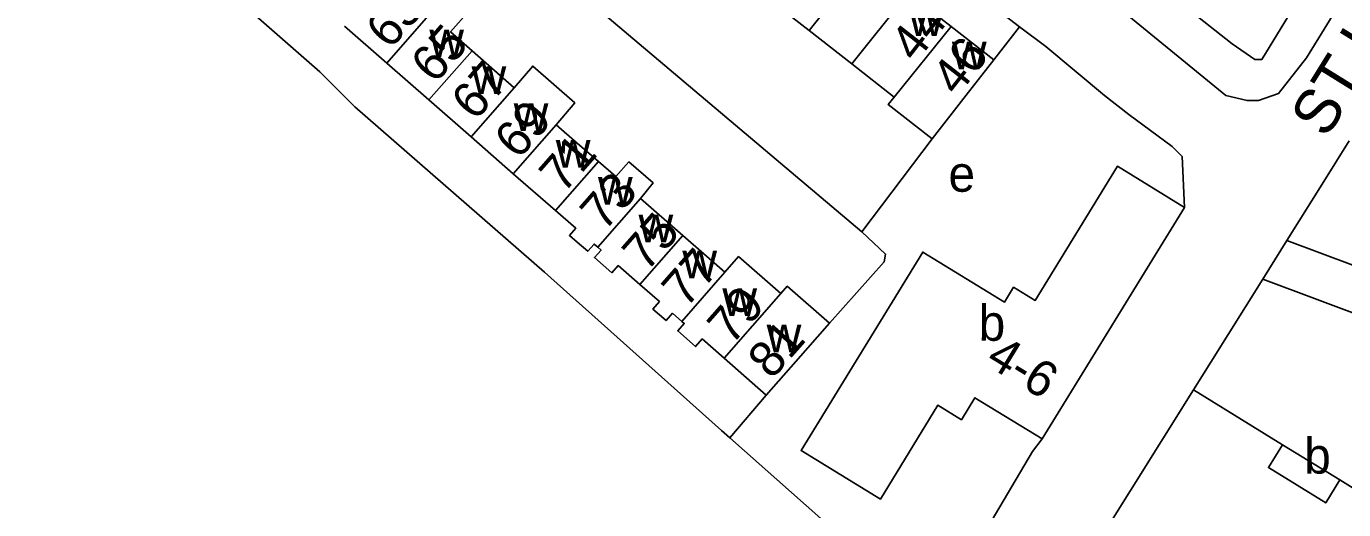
# Model space of a CAD drawing. Extents: x 162804 to 165059, y 381530 to 382901.
# Drawn here: x 162938.5 to 163085.6, y 381854.4 to 381908.3 of the extents above; entities that cross this region are included whole.
import ezdxf

# ---------------------------------------------------------------- set-up
doc = ezdxf.new("R2010")
doc.units = 0
for name, color, linetype in [('BLT_Basislijn', 7, 'Continuous'), ('BLT_Bebouwing', 7, 'Continuous'), ('BLT_Centroide', 7, 'Continuous'), ('BLT_Huisnummer', 7, 'Continuous'), ('BLT_Huisnummer_ tussenligend', 7, 'Continuous'), ('BLT_Huisnummer_reeks', 7, 'Continuous'), ('BLT_Onderverdeling_panden', 7, 'Continuous'), ('BLT_Straatnaam', 7, 'Continuous')]:
    doc.layers.add(name, color=color, linetype=linetype)

msp = doc.modelspace()

# ---------------------------------------------------------------- linework, layer by layer
at = {"layer": 'BLT_Basislijn'}
for p, q in [((162982.74, 381926.86), (163031.79, 381885.39)), ((163046.52, 381904.6), (163049.39, 381908.29)), ((163058.86, 381900.61), (163061.6, 381898.48)), ((163031.79, 381885.39), (163039.63, 381895.79)), ((163083.34, 381891.02), (163086.18, 381895.57)), ((163079.23, 381884.44), (163083.34, 381891.02)), ((163076.53, 381880.11), (163079.23, 381884.44)), ((163068.81, 381867.75), (163076.53, 381880.11)), ((163017.03, 381862.36), (163021.12, 381867.16)), ((163051.03, 381839.3), (163068.81, 381867.75)), ((163078.76, 381861.61), (163068.81, 381867.75)), ((163085.15, 381857.68), (163092.38, 381853.12))]:
    msp.add_line(p, q, dxfattribs=at)
for points in [[(163142.62, 381959.14), (163116.47, 381889.89), (163110.52, 381874.65), (163109.75, 381873.99), (163108.12, 381873.63), (163079.23, 381884.44)], [(163104.58, 381951.95), (163107.72, 381949.86), (163108.33, 381948.97), (163107.96, 381947.96), (163081.42, 381904.82), (163078.3, 381900.84), (163076.07, 381900.06), (163074.79, 381900.06), (163072.4, 381900.61), (163058.73, 381911.86), (163052.24, 381916.83)], [(163104.58, 381951.95), (163102.76, 381948.29), (163098.1, 381940.15), (163076.45, 381904.65), (163075.65, 381904.65), (163073.11, 381906.41), (163055.05, 381920.69)], [(163049.39, 381908.29), (163048.27, 381909.14), (163024.93, 381927.03), (163020.58, 381930.61), (162999.06, 381947.28)], [(162933.29, 381940.41), (162931.69, 381938.6), (162943.06, 381927.99), (162971.29, 381903.26), (162975.18, 381899.34), (162996.37, 381880.88), (163016.11, 381863.18), (163017.03, 381862.36)], [(163049.39, 381908.29), (163052.32, 381906.08), (163058.86, 381900.61)], [(163067.81, 381888.12), (163067.53, 381893.82), (163066.42, 381894.91), (163061.6, 381898.48)], [(163031.79, 381885.39), (163034.44, 381882.91), (163034.28, 381882.02), (163028.16, 381875.19)], [(163104.6, 381849.45), (163107.64, 381865.58), (163108.17, 381867.76), (163107.76, 381868.42), (163076.53, 381880.11)], [(163051.91, 381862.27), (163050.85, 381860.84), (163040.25, 381842.95), (163039.32, 381842.6), (163017.03, 381862.36)]]:
    msp.add_lwpolyline(points, dxfattribs=at)
at = {"layer": 'BLT_Bebouwing'}
for p, q in [((163021.15, 381911.59), (163025.9, 381907.87)), ((163036.97, 381912.07), (163041.74, 381908.34)), ((162974.03, 381908.36), (162978.74, 381904.24)), ((163041.74, 381908.34), (163046.52, 381904.6)), ((162992.97, 381901.48), (162988.27, 381905.61)), ((162978.74, 381904.24), (162983.45, 381900.12)), ((163030.65, 381904.16), (163035.4, 381900.45)), ((162983.45, 381900.12), (162988.16, 381896)), ((162988.16, 381896), (162992.87, 381891.88)), ((162992.87, 381891.88), (162997.58, 381887.77)), ((163007.09, 381889.11), (163011.79, 381884.99)), ((163011.79, 381884.99), (163016.5, 381880.87)), ((163016.41, 381871.29), (163021.12, 381867.16)), ((163085.15, 381857.68), (163078.76, 381861.61))]:
    msp.add_line(p, q, dxfattribs=at)
for points in [[(162988.27, 381905.61), (162985.88, 381907.74), (162988.19, 381910.38), (162985.88, 381912.39)], [(163025.9, 381907.87), (163030.65, 381904.16)], [(162997.67, 381897.36), (162999.74, 381899.8), (162995.05, 381903.91), (162992.97, 381901.48)], [(163039.63, 381895.79), (163043.44, 381900.66), (163046.52, 381904.6)], [(163035.4, 381900.45), (163034.74, 381899.6), (163039.63, 381895.79)], [(163002.38, 381893.23), (163000, 381895.31), (162997.67, 381897.36)], [(163002.38, 381893.23), (163004.33, 381891.56), (163005.77, 381893.21), (163008.47, 381890.85), (163007.09, 381889.11)], [(163051.91, 381862.27), (163044.41, 381866.86), (163042.9, 381864.39), (163040.26, 381866.01), (163033.86, 381855.54), (163025.01, 381860.95), (163038.58, 381883.13), (163047.71, 381877.54), (163048.73, 381879.2), (163051.14, 381877.72), (163060.31, 381892.71), (163067.81, 381888.12)], [(162997.58, 381887.77), (162999.84, 381885.79), (162999.14, 381884.99), (163000, 381884.25), (163001.18, 381883.22), (163001.89, 381884.03), (163002.3, 381883.66)], [(163067.81, 381888.12), (163051.91, 381862.27)], [(163002.3, 381883.66), (163002.67, 381883.35), (163001.93, 381882.51), (163003.87, 381880.81), (163004.59, 381881.62), (163006.99, 381879.52)], [(163016.5, 381880.87), (163018.03, 381882.62), (163022.74, 381878.5)], [(163006.99, 381879.52), (163009.19, 381877.6), (163008.46, 381876.76), (163009.93, 381875.48), (163010.65, 381876.3), (163011.69, 381875.39)], [(163022.74, 381878.5), (163023.45, 381879.31), (163028.16, 381875.19)], [(163011.69, 381875.39), (163011.96, 381875.16), (163011.23, 381874.32), (163013.23, 381872.57), (163013.97, 381873.42), (163016.41, 381871.29)], [(163021.12, 381867.16), (163024.42, 381870.92), (163028.16, 381875.19)], [(163078.76, 381861.61), (163077.18, 381859.05), (163083.57, 381855.11), (163085.15, 381857.68)]]:
    msp.add_lwpolyline(points, dxfattribs=at)
at = {"layer": 'BLT_Onderverdeling_panden'}
for p, q in [((163025.9, 381907.87), (163032.19, 381915.8)), ((162978.74, 381904.24), (162985.88, 381912.39)), ((163030.65, 381904.16), (163036.97, 381912.07)), ((163035.4, 381900.45), (163041.74, 381908.34)), ((162983.45, 381900.12), (162988.27, 381905.61)), ((162988.16, 381896), (162992.97, 381901.48)), ((162992.87, 381891.88), (162997.67, 381897.36)), ((162997.58, 381887.77), (163002.38, 381893.23)), ((163002.3, 381883.66), (163007.09, 381889.11)), ((163006.99, 381879.52), (163011.79, 381884.99)), ((163011.69, 381875.39), (163016.5, 381880.87)), ((163016.41, 381871.29), (163022.74, 381878.5))]:
    msp.add_line(p, q, dxfattribs=at)

# ---------------------------------------------------------------- texts
at = {"layer": 'BLT_Centroide'}
for s, p in [('w', (163037.06, 381907.28)), ('w', (162983.5, 381904.92)), ('w', (163041.84, 381903.55)), ('w', (162988.22, 381900.8)), ('w', (162992.92, 381896.67)), ('w', (162997.62, 381892.56)), ('e', (163041.45, 381889.87)), ('w', (163002.33, 381888.44)), ('w', (163006.86, 381884.23)), ('w', (163011.75, 381880.2)), ('w', (163016.22, 381876)), ('b', (163044.82, 381873.22)), ('w', (163021.16, 381871.94)), ('b', (163081.16, 381858.38))]:
    msp.add_text(s, height=4, dxfattribs=at).set_placement(p)
at = {"layer": 'BLT_Huisnummer'}
for s, rotation, p in [('65', 48.7093, (162984.13, 381901.82)), ('46', 51.9863, (163042.45, 381900.42)), ('69', 48.7109, (162993.45, 381893.36)), ('73', 48.7067, (163003.02, 381885.32)), ('77', 48.7085, (163012.14, 381876.75)), ('81', 48.7947, (163021.73, 381868.79))]:
    msp.add_text(s, height=4, rotation=rotation, dxfattribs=at).set_placement(p)
at = {"layer": 'BLT_Huisnummer_ tussenligend'}
for s, rotation, p in [('63', 48.7055, (162979.11, 381905.66)), ('44', 51.986, (163037.81, 381904.18)), ('67', 48.7093, (162988.64, 381897.67)), ('71', 48.7109, (162998.46, 381889.55)), ('75', 48.7067, (163007.73, 381880.79)), ('79', 48.7085, (163017.23, 381872.61))]:
    msp.add_text(s, height=4, rotation=rotation, dxfattribs=at).set_placement(p)
at = {"layer": 'BLT_Huisnummer_reeks'}
msp.add_text('4-6', height=4, rotation=328.5485, dxfattribs=at).set_placement((163045.44, 381870.62))
at = {"layer": 'BLT_Straatnaam'}
msp.add_text('ST LIDWINASTRAAT', height=5, rotation=58.1784, dxfattribs=at).set_placement((163083.63, 381895.69))

doc.saveas('drawing.dxf')
